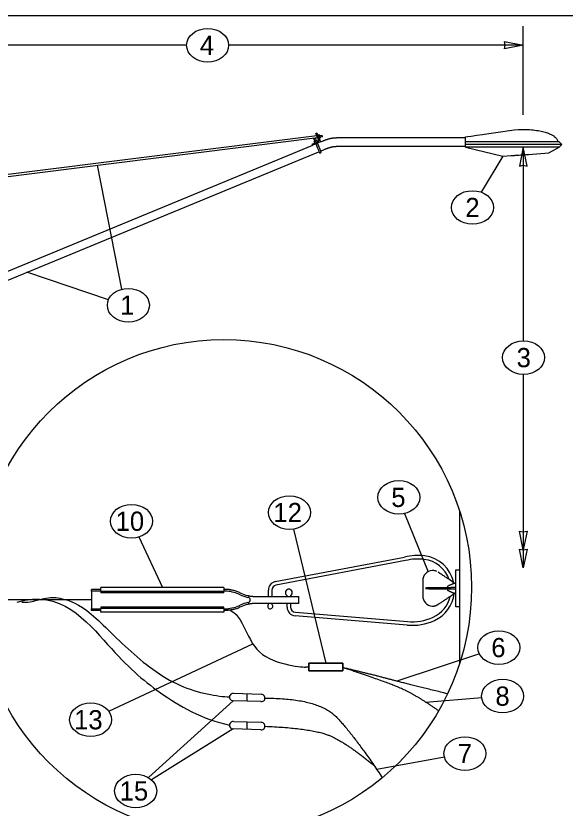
# Model space of a CAD drawing. Extents: x 99862 to 104211, y 98939 to 102076.
# Drawn here: x 100331 to 100788, y 101416 to 102076 of the extents above; entities that cross this region are included whole.
import ezdxf

# ---------------------------------------------------------------- set-up
doc = ezdxf.new("R2010")
doc.units = 0
for name, color, linetype in [('Level 1', 7, 'Continuous'), ('Level 12', 7, 'Continuous'), ('Level 13', 7, 'Continuous'), ('Level 14', 7, 'Continuous'), ('Level 15', 7, 'Continuous'), ('Level 16', 7, 'Continuous'), ('Level 17', 7, 'Continuous'), ('Level 19', 7, 'Continuous'), ('Level 20', 7, 'Continuous'), ('Level 32', 7, 'Continuous'), ('Level 34', 7, 'Continuous'), ('Level 35', 7, 'Continuous'), ('Level 38', 7, 'Continuous'), ('Level 40', 7, 'Continuous'), ('Level 49', 7, 'Continuous'), ('Level 7', 7, 'Continuous')]:
    doc.layers.add(name, color=color, linetype=linetype)

msp = doc.modelspace()

# ---------------------------------------------------------------- linework, layer by layer
at = {"layer": 'Level 1'}
msp.add_line((100700.45, 101663.9), (100700.45, 101536.02), dxfattribs=at)
msp.add_lwpolyline([(99862, 99999.5), (103151, 99999.5), (103151, 102075.5), (99862, 102075.5)], close=True, dxfattribs=at)
at = {"layer": 'Level 12'}
msp.add_line((100394.28, 101589.38), (100298.68, 101589.38), dxfattribs=at)
for points, degree in [([(100505.26, 101582.05), (100521.3, 101580.04), (100521.5, 101535.42), (100572.52, 101533.48), (100572.52, 101533.48)], 3), ([(100575.16, 101533.49), (100574.28, 101533.49), (100573.4, 101533.48), (100572.52, 101533.48)], 2), ([(100683.17, 101497.2), (100665.04, 101509.85), (100639.93, 101521.13), (100603.43, 101533.1)], 2), ([(100690.58, 101511.31), (100658.32, 101519.11), (100628.56, 101527.1), (100603.43, 101533.1)], 2), ([(100538.69, 101507.68), (100583.25, 101507.68), (100613.45, 101475.81), (100636.31, 101441.5)], 2), ([(100538.69, 101484.26), (100578.89, 101482.62), (100608.08, 101469.45), (100629.21, 101451.71)], 2)]:
    msp.add_open_spline(points, degree=degree, dxfattribs=at)
at = {"layer": 'Level 13'}
for p, q in [((100394.28, 101596.7), (100394.28, 101598.17)), ((100394.28, 101596.7), (100394.28, 101582.06)), ((100517.91, 101593.68), (100516.94, 101594.14)), ((100517.55, 101595.47), (100518.53, 101595.01)), ((100566.77, 101586.45), (100566.77, 101592.31)), ((100516.94, 101584.62), (100517.91, 101585.07)), ((100394.28, 101580.59), (100394.28, 101582.06)), ((100518.53, 101583.74), (100517.55, 101583.29))]:
    msp.add_line(p, q, dxfattribs=at)
for centre, radius, start, end in [((100505.26, 101568.87), 27.83, 89.12593, 90.00049), ((100505.26, 101568.87), 27.83, 65.18429, 89.12593), ((100505.26, 101568.87), 29.3, 65.1843, 71.72722), ((100530.83, 101621.61), 30.76, 245.18431, 257.80283), ((100530.83, 101621.61), 29.3, 245.1843, 257.18257), ((100530.83, 101557.15), 30.76, 102.19689, 114.81571), ((100530.83, 101557.15), 29.3, 102.8171, 114.8157), ((100505.26, 101609.88), 27.83, 269.99999, 294.81569), ((100505.26, 101609.88), 29.3, 288.27479, 294.8157)]:
    msp.add_arc(centre, radius, start, end, dxfattribs=at)
for points, degree in [([(100402.17, 101598.17), (100398.23, 101598.17), (100394.28, 101598.17)], 2), ([(100505.26, 101598.17), (100504.86, 101598.17), (100504.46, 101598.17)], 2), ([(100505.72, 101598.17), (100505.49, 101598.17), (100505.26, 101598.17)], 2), ([(100514.44, 101596.69), (100513.03, 101597.16), (100511.6, 101597.52), (100508.68, 101598.01), (100507.2, 101598.14), (100505.72, 101598.17)], 3), ([(100402.17, 101596.7), (100399.54, 101596.7), (100396.91, 101596.7), (100394.28, 101596.7)], 2), ([(100505.26, 101596.7), (100504.99, 101596.7), (100504.73, 101596.7), (100504.46, 101596.7)], 2), ([(100524.33, 101593.04), (100524.61, 101592.97), (100524.9, 101592.91), (100525.47, 101592.8), (100525.73, 101592.75), (100526.24, 101592.67), (100526.47, 101592.63), (100526.76, 101592.59), (100526.85, 101592.58), (100527.01, 101592.56), (100527.09, 101592.55), (100527.21, 101592.53), (100527.31, 101592.52), (100527.39, 101592.51), (100527.41, 101592.51), (100527.42, 101592.51), (100527.42, 101592.51), (100527.42, 101592.51), (100527.42, 101592.51), (100527.42, 101592.51), (100527.42, 101592.51), (100527.42, 101592.51), (100527.45, 101592.5), (100527.49, 101592.5), (100527.62, 101592.48), (100527.71, 101592.47), (100527.93, 101592.45), (100528.06, 101592.44), (100528.36, 101592.41), (100528.53, 101592.4), (100528.9, 101592.37), (100529.11, 101592.36), (100529.55, 101592.34), (100529.79, 101592.33), (100530.29, 101592.31), (100530.55, 101592.31), (100530.83, 101592.31)], 3), ([(100530.83, 101592.31), (100531.25, 101592.31), (100531.68, 101592.31), (100532.35, 101592.31), (100532.58, 101592.31), (100532.93, 101592.31), (100533.16, 101592.31), (100533.39, 101592.31), (100534.42, 101592.31), (100537.19, 101592.31), (100543.63, 101592.31), (100551, 101592.31), (100556.99, 101592.31), (100559.52, 101592.31), (100560.33, 101592.31), (100560.79, 101592.31), (100561.02, 101592.31), (100561.59, 101592.31), (100562.05, 101592.31), (100562.72, 101592.31), (100562.95, 101592.31), (100563.38, 101592.31), (100563.8, 101592.31), (100564.39, 101592.31), (100564.76, 101592.31), (100565.27, 101592.31), (100565.57, 101592.31), (100565.96, 101592.31), (100566.07, 101592.31), (100566.28, 101592.31), (100566.37, 101592.31), (100566.6, 101592.31), (100566.7, 101592.31), (100566.76, 101592.31), (100566.77, 101592.31), (100566.77, 101592.31), (100566.77, 101592.31), (100566.77, 101592.31), (100566.77, 101592.31), (100566.77, 101592.31), (100566.77, 101592.31)], 3), ([(100530.83, 101586.45), (100530.28, 101586.45), (100529.79, 101586.43), (100529.12, 101586.4), (100528.92, 101586.39), (100528.54, 101586.36), (100528.37, 101586.35), (100528.07, 101586.32), (100527.94, 101586.31), (100527.72, 101586.28), (100527.63, 101586.28), (100527.5, 101586.26), (100527.45, 101586.26), (100527.41, 101586.25), (100527.42, 101586.25), (100527.42, 101586.25), (100527.42, 101586.25), (100527.42, 101586.25), (100527.42, 101586.25), (100527.42, 101586.25), (100527.41, 101586.25), (100527.39, 101586.25), (100527.35, 101586.24), (100527.27, 101586.23), (100527.21, 101586.23), (100527.09, 101586.21), (100527.02, 101586.2), (100526.86, 101586.18), (100526.59, 101586.14), (100526.25, 101586.09), (100525.74, 101586.01), (100525.47, 101585.96), (100524.9, 101585.85), (100524.61, 101585.78), (100524.33, 101585.72)], 3), ([(100566.77, 101586.45), (100566.77, 101586.45), (100566.77, 101586.45), (100566.77, 101586.45), (100566.77, 101586.45), (100566.77, 101586.45), (100566.77, 101586.45), (100566.77, 101586.45), (100566.74, 101586.45), (100566.69, 101586.45), (100566.59, 101586.45), (100566.4, 101586.45), (100566.1, 101586.45), (100565.72, 101586.45), (100565.58, 101586.45), (100565.28, 101586.45), (100564.97, 101586.45), (100564.61, 101586.45), (100564.24, 101586.45), (100563.65, 101586.45), (100563.01, 101586.45), (100562.34, 101586.45), (100562.11, 101586.45), (100561.65, 101586.45), (100561.42, 101586.45), (100560.96, 101586.45), (100560.73, 101586.45), (100560.27, 101586.45), (100559.58, 101586.45), (100557.04, 101586.45), (100551.05, 101586.45), (100543.68, 101586.45), (100537.22, 101586.45), (100534.46, 101586.45), (100533.42, 101586.45), (100533.31, 101586.45), (100533.08, 101586.45), (100532.73, 101586.45), (100532.16, 101586.45), (100531.7, 101586.45), (100531.26, 101586.45), (100531.04, 101586.45), (100530.83, 101586.45)], 3), ([(100394.28, 101582.06), (100396.91, 101582.06), (100399.54, 101582.06), (100402.17, 101582.06)], 2), ([(100402.17, 101580.59), (100398.23, 101580.59), (100394.28, 101580.59)], 2), ([(100504.46, 101582.06), (100504.73, 101582.06), (100504.99, 101582.06), (100505.26, 101582.06)], 2), ([(100505.26, 101580.59), (100504.86, 101580.59), (100504.46, 101580.59)], 2), ([(100514.44, 101582.06), (100512.96, 101581.58), (100511.45, 101581.21), (100508.37, 101580.71), (100506.81, 101580.59), (100505.26, 101580.59)], 3)]:
    msp.add_open_spline(points, degree=degree, dxfattribs=at)
at = {"layer": 'Level 14'}
for p, q in [((100504.46, 101599.64), (100402.17, 101599.64)), ((100402.17, 101596.41), (100402.17, 101599.64)), ((100504.46, 101599.64), (100504.46, 101596.41)), ((100504.46, 101596.41), (100402.17, 101596.41)), ((100402.17, 101596.41), (100402.17, 101595.24)), ((100504.46, 101595.24), (100402.17, 101595.24)), ((100504.46, 101595.24), (100504.46, 101596.41)), ((100504.46, 101583.52), (100402.17, 101583.52)), ((100402.17, 101583.52), (100402.17, 101582.34)), ((100504.46, 101582.34), (100402.17, 101582.34)), ((100402.17, 101579.12), (100402.17, 101582.34)), ((100504.46, 101579.12), (100402.17, 101579.12)), ((100504.46, 101582.34), (100504.46, 101583.52)), ((100504.46, 101582.34), (100504.46, 101579.12))]:
    msp.add_line(p, q, dxfattribs=at)
at = {"layer": 'Level 15'}
for p, q in [((100753.64, 101993.04), (100753.64, 102067.04)), ((100473.47, 102051.04), (100226.45, 102051.04)), ((100753.64, 102051.04), (100508.47, 102051.04)), ((100753.64, 101966.15), (100753.64, 101805.08)), ((100736.58, 101958.69), (100718.53, 101928.78)), ((100419.61, 101848), (100399.38, 101951.23)), ((100408.48, 101839.29), (100340.49, 101862.09)), ((100753.64, 101777.08), (100753.64, 101616.02)), ((100654.83, 101661.28), (100674.46, 101612.89)), ((100562.37, 101648.4), (100589.3, 101536.7)), ((100433.71, 101641.79), (100453.32, 101599.64)), ((100547.13, 101604.67), (100654.84, 101625.01)), ((100655.55, 101622.16), (100547.84, 101601.83)), ((100547.84, 101601.83), (100547.84, 101601.83)), ((100541.58, 101592.31), (100541.58, 101597.57)), ((100544.51, 101597.57), (100544.51, 101592.31)), ((100544.51, 101597.57), (100544.51, 101597.57)), ((100557.06, 101592.99), (100557.06, 101592.99)), ((100557.06, 101592.31), (100557.06, 101592.99)), ((100559.99, 101592.99), (100559.99, 101592.31)), ((100541.58, 101585.61), (100541.58, 101586.45)), ((100541.58, 101585.61), (100541.58, 101585.61)), ((100544.51, 101586.45), (100544.51, 101585.61)), ((100557.06, 101583.48), (100557.06, 101586.45)), ((100559.99, 101586.45), (100559.99, 101583.48)), ((100559.99, 101583.48), (100559.99, 101583.48)), ((100564.02, 101579.1), (100564.02, 101579.1)), ((100564.02, 101579.1), (100657.24, 101571.34)), ((100657, 101568.42), (100563.78, 101576.18)), ((100408.71, 101496.77), (100528.62, 101552.82)), ((100717.12, 101544.43), (100648.45, 101521.83)), ((100719.02, 101507.94), (100672.37, 101504.09)), ((100512.18, 101505.45), (100441.67, 101441.58)), ((100512.18, 101482.03), (100444.22, 101439.69)), ((100688, 101458.57), (100631.63, 101448.33))]:
    msp.add_line(p, q, dxfattribs=at)
for points in [[(100753.64, 102051.04), (100737.92, 102047.96), (100738.65, 102051.04), (100737.92, 102054.13)], [(100753.64, 101966.15), (100750.56, 101950.42), (100753.64, 101951.15), (100756.73, 101950.42)], [(100753.64, 101631.01), (100750.56, 101646.74), (100753.64, 101646.01), (100756.73, 101646.74)], [(100753.64, 101616.02), (100750.56, 101631.74), (100753.64, 101631.01), (100756.73, 101631.74)]]:
    msp.add_lwpolyline(points, close=True, dxfattribs=at)
msp.add_circle((100504.52, 101599.96), 206.11, dxfattribs=at)
for centre, radius, start, end in [((100665.98, 101580.61), 45.78, 83.055, 104.08872), ((100668.11, 101598.06), 28.2, 11.5094, 83.055), ((100665.98, 101580.61), 42.85, 83.055, 104.08872), ((100668.11, 101598.06), 25.27, 19.35909, 83.055), ((100548.91, 101597.57), 7.32, 104.08872, 180), ((100548.91, 101597.57), 4.39, 104.08872, 180), ((100558.53, 101595.43), 2.85, 300.95856, 180), ((100524.33, 101589.38), 2.16, 270.00024, 90.00024), ((100558.53, 101595.43), 2.85, 180, 239.04144), ((100668.11, 101598.06), 25.27, 294.58609, 346.76509), ((100668.11, 101598.06), 28.2, 294.58609, 353.42392), ((100543.05, 101584.13), 2.08, 134.76019, 180), ((100543.05, 101584.13), 2.08, 180, 45.23981), ((100564.39, 101583.48), 7.32, 180, 265.24382), ((100564.39, 101583.48), 4.39, 180, 265.24382), ((100660.8, 101614.04), 45.78, 265.24382, 294.58609), ((100660.8, 101614.04), 42.85, 265.24382, 294.58609)]:
    msp.add_arc(centre, radius, start, end, dxfattribs=at)
at = {"layer": 'Level 16'}
for points in [[(100332.44, 101587.46), (100368.1, 101599.03), (100413.35, 101543.65), (100447.55, 101512.82), (100486.71, 101489.86), (100509.15, 101485.25)], [(100336.39, 101587.46), (100343.78, 101587.46), (100350.59, 101589.83), (100358.8, 101591.37), (100365.07, 101591.91), (100388.54, 101585.84), (100423.2, 101548.04), (100467.05, 101513.99), (100499.5, 101509.09), (100509.15, 101508.67)]]:
    msp.add_open_spline(points, degree=3, dxfattribs=at)
at = {"layer": 'Level 17'}
for p, q in [((100512.37, 101511.69), (100535.64, 101510.96)), ((100523.74, 101505.09), (100524, 101511.33)), ((100535.31, 101504.74), (100512.18, 101505.45)), ((100512.37, 101488.27), (100535.64, 101487.55)), ((100523.74, 101481.68), (100524, 101487.91)), ((100535.31, 101481.32), (100512.18, 101482.03))]:
    msp.add_line(p, q, dxfattribs=at)
for points in [[(100575.16, 101530.45), (100603.43, 101530.45), (100603.43, 101534.17), (100603.43, 101536.7), (100575.16, 101536.7), (100575.16, 101534.17)], [(100575.16, 101536.7), (100603.43, 101536.7), (100603.43, 101530.45), (100575.16, 101530.45)]]:
    msp.add_lwpolyline(points, close=True, dxfattribs=at)
for centre, start, end in [((100512.27, 101508.57), 88.20586, 268.23543), ((100535.57, 101507.85), 265.14512, 88.82592), ((100512.27, 101485.15), 88.20586, 268.23543), ((100535.57, 101484.43), 265.14512, 88.82592)]:
    msp.add_arc(centre, 3.12, start, end, dxfattribs=at)
at = {"layer": 'Level 19'}
for p, q in [((100782.38, 101970.67), (100705.54, 101970.67)), ((100785.78, 101968.41), (100705.54, 101968.41)), ((100783.52, 101970.67), (100782.38, 101970.67)), ((100705.54, 101966.15), (100736.58, 101958.69)), ((100783.52, 101966.15), (100705.54, 101966.15)), ((100757.96, 101960.23), (100774.8, 101961.44)), ((100774.8, 101961.44), (100783.52, 101966.15)), ((100736.58, 101958.69), (100743.51, 101959.19))]:
    msp.add_line(p, q, dxfattribs=at)
for points in [[(100730.89, 101978.51), (100746.03, 101980.7)], [(100746.03, 101980.7), (100749.46, 101980.98)], [(100749.46, 101980.98), (100753.64, 101981.04)], [(100705.54, 101974.79), (100707.39, 101975.07)], [(100707.39, 101975.07), (100710.22, 101975.48)], [(100710.22, 101975.48), (100714.92, 101976.17)], [(100714.92, 101976.17), (100719.57, 101976.85)], [(100719.57, 101976.85), (100724.92, 101977.63)], [(100724.92, 101977.63), (100730.89, 101978.51)], [(100785.78, 101968.41), (100784.65, 101969.54), (100783.52, 101970.67)], [(100783.52, 101966.15), (100784.65, 101967.28), (100785.78, 101968.41)]]:
    msp.add_lwpolyline(points, dxfattribs=at)
for points, degree in [([(100753.64, 101981.04), (100756.17, 101981.04), (100760.41, 101980.83), (100766.28, 101980.03), (100770.95, 101978.99), (100774.7, 101977.75), (100777.58, 101976.42), (100779.48, 101975.22), (100780.87, 101973.97), (100781.69, 101972.95), (100782.24, 101971.8), (100782.37, 101971.06), (100782.38, 101970.67)], 3), ([(100705.54, 101970.58), (100705.54, 101974.79), (100705.54, 101974.79)], 2), ([(100705.54, 101968.41), (100705.54, 101969.17), (100705.54, 101969.92), (100705.54, 101970.67)], 2), ([(100705.54, 101966.15), (100705.54, 101966.9), (100705.54, 101967.65), (100705.54, 101968.41)], 2), ([(100743.51, 101959.19), (100745.34, 101959.32), (100747.12, 101959.45), (100748.82, 101959.57), (100750.73, 101959.71), (100754.29, 101959.97), (100757.96, 101960.23)], 3)]:
    msp.add_open_spline(points, degree=degree, dxfattribs=at)
at = {"layer": 'Level 20'}
for centre in [(100490.97, 102051.04), (100711.37, 101916), (100425.01, 101834.68), (100753.84, 101791.08), (100650.09, 101674.76), (100559.06, 101662.14), (100427.6, 101654.91), (100733.3, 101549.75), (100736.43, 101509.34), (100393.6, 101489.7), (100705.09, 101461.58), (100431.1, 101430.42)]:
    msp.add_ellipse(centre, major_axis=(-17.5, 0), ratio=0.8, dxfattribs=at)
at = {"layer": 'Level 32'}
for p, q in [((100705.16, 101973.93), (100602.22, 101973.93)), ((100266.99, 101839.23), (100578.4, 101967.79)), ((100285.11, 101839.23), (100583.62, 101962.46)), ((100585.06, 101963.06), (100587.65, 101964.12)), ((100602.22, 101967.01), (100705.16, 101967.01))]:
    msp.add_line(p, q, dxfattribs=at)
msp.add_ellipse((100705.16, 101970.47), major_axis=(0, 3.46), ratio=0.000166, start_param=6.283185, end_param=9.424778, dxfattribs=at)
for points in [[(100602.22, 101973.93), (100596.34, 101973.93), (100590.46, 101972.76), (100585.02, 101970.52)], [(100587.65, 101964.12), (100592.25, 101966.03), (100597.24, 101967.01), (100602.22, 101967.01)]]:
    msp.add_open_spline(points, degree=2, dxfattribs=at)
at = {"layer": 'Level 34'}
for p, q in [((100579.27, 101973.01), (100580.1, 101970.98)), ((100581.55, 101971.58), (100580.71, 101973.6)), ((100580.98, 101968.85), (100582.03, 101966.32)), ((100583.47, 101966.92), (100582.43, 101969.45))]:
    msp.add_line(p, q, dxfattribs=at)
for centre, start_param, end_param in [((100579.99, 101973.3), 3.141593, 6.283177), ((100579.99, 101973.3), 6.283177, 6.283185), ((100582.75, 101966.62), 6.283177, 6.283222)]:
    msp.add_ellipse(centre, major_axis=(0.722, 0.298), ratio=0.000371, start_param=start_param, end_param=end_param, dxfattribs=at)
for points in [[(100582.03, 101966.32), (100582.52, 101965.13), (100583.16, 101963.57), (100583.54, 101962.64), (100583.62, 101962.46)], [(100583.62, 101962.46), (100583.74, 101962.14), (100583.83, 101961.92), (100583.85, 101961.88), (100583.99, 101961.61), (100584.45, 101961.32), (100585.13, 101961.52), (100585.4, 101961.98), (100585.33, 101962.4), (100585.29, 101962.49), (100585.24, 101962.62), (100584.63, 101964.11), (100583.76, 101966.22), (100583.47, 101966.92)]]:
    msp.add_open_spline(points, degree=3, dxfattribs=at)
at = {"layer": 'Level 35'}
for p, q in [((100580.92, 101977.7), (100581.89, 101978.1)), ((100583.66, 101971.08), (100580.92, 101977.7)), ((100581.89, 101978.1), (100585.02, 101970.52)), ((100578, 101968.75), (100583.66, 101971.08)), ((100578.4, 101967.79), (100578, 101968.75)), ((100585.02, 101970.52), (100578.4, 101967.79))]:
    msp.add_line(p, q, dxfattribs=at)
at = {"layer": 'Level 38'}
for p, q in [((100669.97, 101605.43), (100669.97, 101592.77)), ((100692.92, 101599.59), (100681.94, 101599.6)), ((100681.94, 101598.6), (100692.91, 101598.61)), ((100697.29, 101599.63), (100694.52, 101599.63)), ((100694.52, 101598.57), (100697.29, 101598.57)), ((100696.42, 101603.13), (100696.42, 101603.13)), ((100696.42, 101595.07), (100696.42, 101595.07))]:
    msp.add_line(p, q, dxfattribs=at)
for centre, start, end in [((100678.41, 101605.43), 94.05297, 179.99344), ((100678.41, 101592.77), 179.99344, 265.93391)]:
    msp.add_arc(centre, 8.44, start, end, dxfattribs=at)
for centre, major_axis, start_param, end_param in [((100685.54, 101599.2), (-13.18, 0), 4.989541, 6.265171), ((100685.54, 101599), (-13.18, 0.01), 0.018014, 1.293644)]:
    msp.add_ellipse(centre, major_axis=major_axis, ratio=0.031999, start_param=start_param, end_param=end_param, dxfattribs=at)
for points, degree in [([(100681.79, 101613.05), (100681.17, 101613.35), (100680.51, 101613.57), (100679.17, 101613.84), (100678.5, 101613.89), (100677.82, 101613.85)], 3), ([(100692.54, 101606.04), (100691.37, 101606.81), (100690.2, 101607.59), (100689.02, 101608.37), (100686.99, 101609.71), (100684.96, 101611.05), (100682.92, 101612.4)], 3), ([(100696.42, 101603.13), (100695.18, 101604.16), (100693.9, 101605.14), (100692.54, 101606.04)], 2), ([(100691.71, 101601.26), (100691.38, 101601.11), (100691.07, 101600.96), (100690.69, 101600.72), (100690.58, 101600.64), (100690.43, 101600.49), (100690.41, 101600.43), (100690.46, 101600.38)], 3), ([(100694.76, 101602.58), (100693.77, 101602.14), (100692.7, 101601.72), (100691.71, 101601.26)], 2), ([(100692.91, 101598.61), (100692.94, 101598.61), (100692.97, 101598.61), (100693, 101598.61), (100693.26, 101598.59), (100693.53, 101598.58), (100693.8, 101598.58), (100694.04, 101598.57), (100694.28, 101598.57), (100694.52, 101598.57)], 3), ([(100694.52, 101599.63), (100694.25, 101599.63), (100693.99, 101599.63), (100693.72, 101599.62), (100693.48, 101599.61), (100693.24, 101599.6), (100693, 101599.59), (100692.97, 101599.59), (100692.94, 101599.59), (100692.92, 101599.59)], 3), ([(100696.42, 101603.13), (100695.9, 101603), (100695.32, 101602.82), (100694.76, 101602.58)], 2), ([(100697.29, 101603.16), (100697, 101603.15), (100696.71, 101603.14), (100696.42, 101603.13)], 2), ([(100682.92, 101585.8), (100684.09, 101586.58), (100685.27, 101587.35), (100686.44, 101588.13), (100688.43, 101589.44), (100690.42, 101590.76), (100692.41, 101592.07), (100692.45, 101592.1), (100692.5, 101592.13), (100692.54, 101592.16)], 3), ([(100690.46, 101597.82), (100690.41, 101597.77), (100690.43, 101597.71), (100690.58, 101597.56), (100690.69, 101597.47), (100691.07, 101597.24), (100691.38, 101597.09), (100691.71, 101596.94)], 3), ([(100691.71, 101596.94), (100692.7, 101596.48), (100693.77, 101596.06), (100694.76, 101595.62)], 2), ([(100692.54, 101592.16), (100693.89, 101593.05), (100695.17, 101594.04), (100696.42, 101595.07)], 2), ([(100694.76, 101595.62), (100695.32, 101595.38), (100695.9, 101595.2), (100696.42, 101595.07)], 2), ([(100696.42, 101595.07), (100696.71, 101595.06), (100697, 101595.05), (100697.29, 101595.04)], 2), ([(100677.81, 101584.36), (100679.17, 101584.26), (100680.55, 101584.55), (100681.78, 101585.16)], 2), ([(100681.78, 101585.16), (100682.17, 101585.35), (100682.55, 101585.56), (100682.92, 101585.8)], 2)]:
    msp.add_open_spline(points, degree=degree, dxfattribs=at)
at = {"layer": 'Level 40'}
msp.add_lwpolyline([(100697.42, 101614.39), (100700.45, 101614.39), (100700.45, 101583.72), (100697.42, 101583.72)], close=True, dxfattribs=at)
at = {"layer": 'Level 49'}
for p, q in [((100581.75, 101975.69), (100205.65, 101928.5)), ((100205.65, 101926.93), (100582.37, 101974.2)), ((100584.12, 101975.99), (100586.24, 101976.26)), ((100586.43, 101974.71), (100584.74, 101974.49))]:
    msp.add_line(p, q, dxfattribs=at)
msp.add_ellipse((100586.33, 101975.48), major_axis=(0.097, -0.775), ratio=0.101579, start_param=6.283177, end_param=9.424785, dxfattribs=at)
at = {"layer": 'Level 7'}
for p, q in [((100583.68, 101976.54), (100582.7, 101976.13)), ((100584.2, 101975.27), (100583.22, 101974.86)), ((100583.75, 101973.59), (100584.72, 101974)), ((100583.88, 101976.59), (100583.85, 101976.61)), ((100584.89, 101974.07), (100584.9, 101974.1)), ((100579.56, 101970.74), (100579.58, 101970.77)), ((100580.04, 101969.59), (100579.64, 101970.57)), ((100580.91, 101971.09), (100581.31, 101970.11)), ((100582.07, 101971.8), (100582.1, 101971.79)), ((100582.18, 101971.61), (100582.58, 101970.64))]:
    msp.add_line(p, q, dxfattribs=at)
for centre, major_axis, ratio, start_param, end_param in [((100584.39, 101975.35), (-0.51, 1.25), 0.000003, 3.226344, 6.283188), ((100580.83, 101971.28), (-1.25, -0.51), 0.000178, 6.282793, 9.424983)]:
    msp.add_ellipse(centre, major_axis=major_axis, ratio=ratio, start_param=start_param, end_param=end_param, dxfattribs=at)
for points, degree in [([(100583.85, 101976.61), (100583.85, 101976.61), (100583.85, 101976.61), (100583.85, 101976.61), (100583.78, 101976.58), (100583.68, 101976.54)], 3), ([(100583.68, 101976.54), (100583.77, 101976.46), (100583.85, 101976.37), (100584, 101976.18), (100584.06, 101976.08), (100584.2, 101975.75), (100584.22, 101975.51), (100584.2, 101975.27)], 3), ([(100584.2, 101975.27), (100584.29, 101975.19), (100584.38, 101975.1), (100584.53, 101974.91), (100584.59, 101974.81), (100584.72, 101974.48), (100584.74, 101974.24), (100584.72, 101974)], 3), ([(100584.72, 101974), (100584.82, 101974.04), (100584.89, 101974.07), (100584.89, 101974.07)], 2), ([(100579.64, 101970.57), (100579.59, 101970.67), (100579.56, 101970.74), (100579.56, 101970.74), (100579.56, 101970.74), (100579.56, 101970.74)], 3), ([(100580.91, 101971.09), (100580.78, 101971.1), (100580.66, 101971.1), (100580.43, 101971.07), (100580.31, 101971.04), (100579.98, 101970.91), (100579.8, 101970.75), (100579.64, 101970.57)], 3), ([(100582.18, 101971.61), (100582.05, 101971.62), (100581.93, 101971.62), (100581.7, 101971.6), (100581.58, 101971.57), (100581.25, 101971.43), (100581.07, 101971.28), (100580.91, 101971.09)], 3), ([(100582.1, 101971.79), (100582.1, 101971.79), (100582.1, 101971.79), (100582.1, 101971.79), (100582.13, 101971.72), (100582.18, 101971.61)], 3)]:
    msp.add_open_spline(points, degree=degree, dxfattribs=at)

# ---------------------------------------------------------------- texts
at = {"layer": 'Level 20'}
for s, p in [('4', (100484.46, 102043.04)), ('2', (100705.38, 101908)), ('1', (100418.14, 101826.69)), ('3', (100748.06, 101783.08)), ('5', (100643.78, 101666.76)), ('12', (100545.63, 101654.14)), ('10', (100414.35, 101646.91)), ('6', (100726.99, 101541.75)), ('8', (100730.42, 101501.34)), ('13', (100379.82, 101481.7)), ('7', (100699.14, 101453.58)), ('15', (100417.72, 101422.43))]:
    msp.add_text(s, height=16, dxfattribs=at).set_placement(p)

doc.saveas('drawing.dxf')
